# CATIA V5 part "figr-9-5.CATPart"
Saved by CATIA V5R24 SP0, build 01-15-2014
Part number: Part1
Bounding box of the stored display mesh (mm): x -71.324 to 69.61, y -211.059 to 0, z 0 to 45
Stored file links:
  D:\KAVITA\CATIA V5-6R2014 Project_ Kavita\CATIA V5-6R2014_partfiles\Partfiles\c09_catia_v5-6r2014_prt\figr-9-5.CATPart
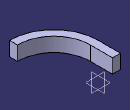
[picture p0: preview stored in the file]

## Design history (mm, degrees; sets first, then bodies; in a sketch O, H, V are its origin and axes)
Body1 (main body)
  Sketch1 on xy-plane, origin (0, 0, 0), H (1, 0, 0), V (0, 1, 0)
    line L1 (0, 0) -> (0, -70.1255)
    arc A1 centre (69.6095, -70.1255) radius 69.6095 from (0, -70.1255) to (69.6095, -139.7351) ccw
    vertical: L1 V
    tangency: A1 L1
  Sketch2 on zx-plane, origin (0, 0, 0), H (-1, 0, 0), V (0, 0, 1)
    point P1 (46.3244, 0)
    line L1 (46.3244, 0) -> (71.3244, 0)
    line L2 (71.3244, 0) -> (71.3244, 45)
    line L3 (71.3244, 45) -> (46.3244, 45)
    line L4 (46.3244, 45) -> (46.3244, 0)
    length L3 = 25
    length L2 = 45
    coincidence: P1 H
    horizontal: L1 H, L3 H
    vertical: L2 V, L4 V
  Rib1: profile Sketch2, centre curve Sketch1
